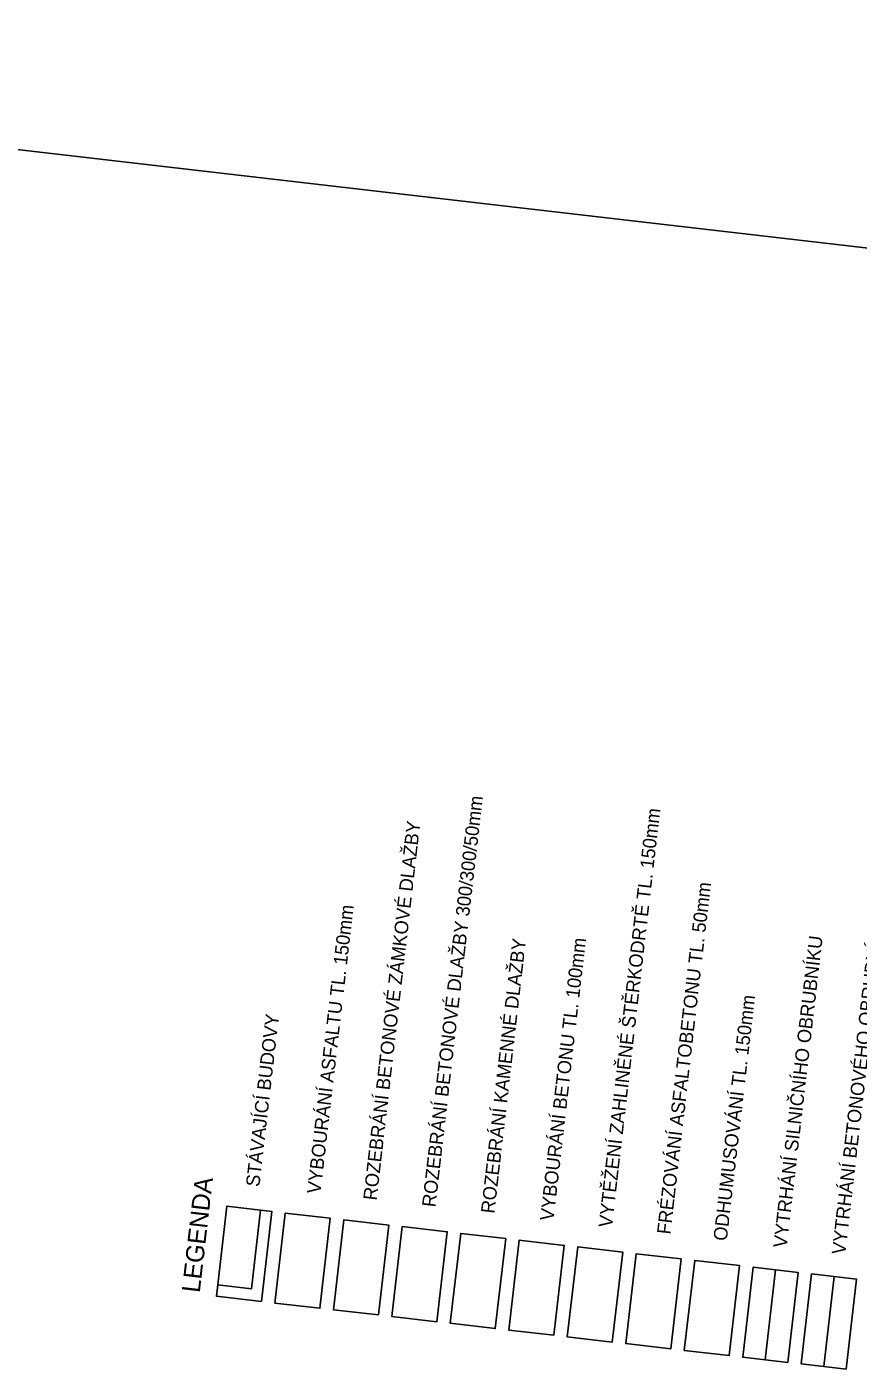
# Model space of a CAD drawing. Extents: x -559989 to -559846, y -1077380 to -1077158.
# Drawn here: x -559917.3 to -559880.6, y -1077217 to -1077157.7 of the extents above; entities that cross this region are included whole.
import ezdxf

# ---------------------------------------------------------------- set-up
doc = ezdxf.new("R2010")
doc.units = 0
doc.layers.add('_Odhumusovani', color=7, linetype='Continuous')
doc.layers.add('rozpiska_ramecek', color=7, linetype='Continuous')

msp = doc.modelspace()

# ---------------------------------------------------------------- linework, layer by layer
at = {"layer": '_Odhumusovani'}
for p, q in [((-559884.697, -1077216.618), (-559884.237, -1077212.645)), ((-559882.114, -1077216.917), (-559881.655, -1077212.944))]:
    msp.add_line(p, q, dxfattribs=at)
for points in [[(-559906.948, -1077214.042), (-559906.488, -1077210.068), (-559908.475, -1077209.838), (-559908.935, -1077213.812)], [(-559908.935, -1077213.812), (-559906.948, -1077214.042), (-559906.488, -1077210.068), (-559906.985, -1077210.011), (-559907.388, -1077213.488), (-559908.878, -1077213.315)], [(-559904.366, -1077214.341), (-559903.906, -1077210.368), (-559905.892, -1077210.138), (-559906.352, -1077214.111)], [(-559906.352, -1077214.111), (-559905.892, -1077210.138), (-559903.906, -1077210.368), (-559904.366, -1077214.341)], [(-559904.366, -1077214.341), (-559903.906, -1077210.368), (-559905.892, -1077210.138), (-559906.352, -1077214.111)], [(-559904.366, -1077214.341), (-559903.906, -1077210.368), (-559905.892, -1077210.138), (-559906.352, -1077214.111)], [(-559901.783, -1077214.64), (-559901.323, -1077210.667), (-559903.31, -1077210.437), (-559903.77, -1077214.41)], [(-559903.77, -1077214.41), (-559903.31, -1077210.437), (-559901.323, -1077210.667), (-559901.783, -1077214.64)], [(-559901.783, -1077214.64), (-559901.323, -1077210.667), (-559903.31, -1077210.437), (-559903.77, -1077214.41)], [(-559901.187, -1077214.709), (-559900.727, -1077210.736), (-559898.74, -1077210.966), (-559899.2, -1077214.939)], [(-559899.2, -1077214.939), (-559898.74, -1077210.966), (-559900.727, -1077210.736), (-559901.187, -1077214.709)], [(-559898.604, -1077215.008), (-559898.144, -1077211.035), (-559896.157, -1077211.265), (-559896.617, -1077215.238)], [(-559896.617, -1077215.238), (-559896.157, -1077211.265), (-559898.144, -1077211.035), (-559898.604, -1077215.008)], [(-559894.035, -1077215.537), (-559893.575, -1077211.564), (-559895.561, -1077211.334), (-559896.021, -1077215.307)], [(-559896.021, -1077215.307), (-559895.561, -1077211.334), (-559893.575, -1077211.564), (-559894.035, -1077215.537)], [(-559894.035, -1077215.537), (-559893.575, -1077211.564), (-559895.561, -1077211.334), (-559896.021, -1077215.307)], [(-559891.452, -1077215.836), (-559890.992, -1077211.863), (-559892.979, -1077211.633), (-559893.439, -1077215.606)], [(-559893.439, -1077215.606), (-559892.979, -1077211.633), (-559890.992, -1077211.863), (-559891.452, -1077215.836)], [(-559891.452, -1077215.836), (-559890.992, -1077211.863), (-559892.979, -1077211.633), (-559893.439, -1077215.606)], [(-559888.869, -1077216.135), (-559888.409, -1077212.162), (-559890.396, -1077211.932), (-559890.856, -1077215.905)], [(-559890.856, -1077215.905), (-559890.396, -1077211.932), (-559888.409, -1077212.162), (-559888.869, -1077216.135)], [(-559888.869, -1077216.135), (-559888.409, -1077212.162), (-559890.396, -1077211.932), (-559890.856, -1077215.905)], [(-559886.286, -1077216.434), (-559885.826, -1077212.461), (-559887.813, -1077212.231), (-559888.273, -1077216.204)], [(-559888.273, -1077216.204), (-559887.813, -1077212.231), (-559885.826, -1077212.461), (-559886.286, -1077216.434)], [(-559886.286, -1077216.434), (-559885.826, -1077212.461), (-559887.813, -1077212.231), (-559888.273, -1077216.204)], [(-559883.704, -1077216.733), (-559883.244, -1077212.76), (-559885.23, -1077212.53), (-559885.69, -1077216.503)], [(-559883.704, -1077216.733), (-559883.244, -1077212.76), (-559885.23, -1077212.53), (-559885.69, -1077216.503)], [(-559881.121, -1077217.032), (-559880.661, -1077213.059), (-559882.648, -1077212.829), (-559883.108, -1077216.802)], [(-559881.121, -1077217.032), (-559880.661, -1077213.059), (-559882.648, -1077212.829), (-559883.108, -1077216.802)]]:
    msp.add_lwpolyline(points, close=True, dxfattribs=at)
at = {"layer": 'rozpiska_ramecek'}
msp.add_line((-559845.922, -1077171.481), (-559964.534, -1077157.745), dxfattribs=at)

# ---------------------------------------------------------------- texts
at = {"layer": '_Odhumusovani'}
for s, height, rotation, p in [('ROZEBRÁNÍ BETONOVÉ DLAŽBY 300/300/50mm', 0.6, 83.3958, (-559899.262, -1077209.899)), ('VYTĚŽENÍ ZAHLINĚNÉ ŠTĚRKODRTĚ TL. 150mm', 0.6, 83.3958, (-559891.468, -1077210.801)), ('ROZEBRÁNÍ BETONOVÉ ZÁMKOVÉ DLAŽBY', 0.6, 83.3958, (-559901.859, -1077209.598)), ('FRÉZOVÁNÍ ASFALTOBETONU TL. 50mm ', 0.6, 83.39431, (-559888.886, -1077211.1)), ('VYBOURÁNÍ ASFALTU TL. 150mm', 0.6, 83.3958, (-559904.342, -1077209.31)), ('VYTRHÁNÍ BETONOVÉHO OBRUBNÍKU', 0.6, 83.3958, (-559881.166, -1077211.994)), ('ROZEBRÁNÍ KAMENNÉ DLAŽBY ', 0.6, 83.3958, (-559896.661, -1077210.179)), ('VYBOURÁNÍ BETONU TL. 100mm', 0.6, 83.3958, (-559894.051, -1077210.502)), ('VYTRHÁNÍ SILNIČNÍHO OBRUBNÍKU', 0.6, 83.3958, (-559883.749, -1077211.695)), ('ODHUMUSOVÁNÍ TL. 150mm ', 0.6, 83.3958, (-559886.395, -1077211.388)), ('STÁVAJÍCÍ BUDOVY', 0.6, 83.39584, (-559907.042, -1077208.998)), ('LEGENDA', 0.8, 83.3958, (-559909.673, -1077213.681))]:
    msp.add_text(s, height=height, rotation=rotation, dxfattribs=at).set_placement(p)

doc.saveas('drawing.dxf')
